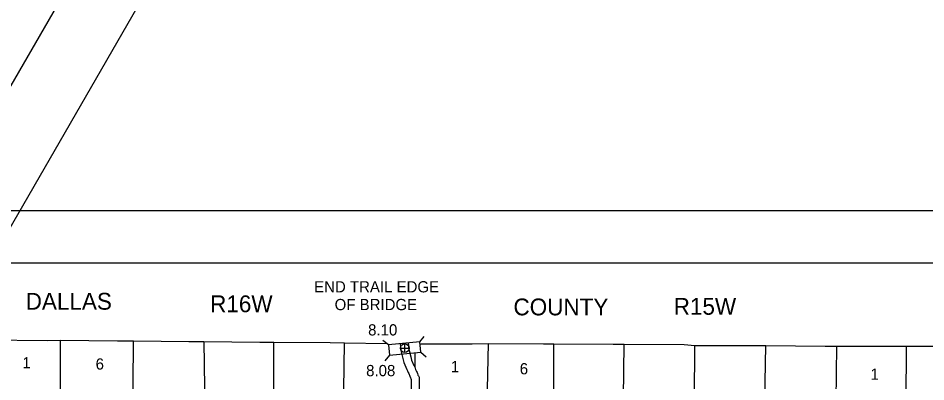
# Model space of a CAD drawing. Extents: x 369523 to 838377, y 495025 to 936819.
# Drawn here: x 667340 to 735755, y 661645 to 689027 of the extents above; entities that cross this region are included whole.
import ezdxf

# ---------------------------------------------------------------- set-up
doc = ezdxf.new("R2010")
doc.units = 0
for name, color, linetype in [('21', 7, 'Continuous'), ('DSN_BRDG_Annotation', 7, 'Continuous'), ('DSN_DRFT_Common-Annotations', 7, 'Continuous'), ('DSN_DRFT_Junk-No-Plot', 7, 'Continuous'), ('Level 1', 7, 'Continuous'), ('Level 15', 7, 'Continuous'), ('Level 21', 7, 'Continuous'), ('Level 22', 7, 'Continuous'), ('Level 6', 7, 'Continuous')]:
    doc.layers.add(name, color=color, linetype=linetype)

msp = doc.modelspace()

# ---------------------------------------------------------------- linework, layer by layer
at = {"layer": '21'}
for p, q in [((715348, 757482), (625588, 602013)), ((623656, 609226), (708796, 756692)), ((542697, 674544), (838377, 674544)), ((833097, 670584), (558537, 670584))]:
    msp.add_line(p, q, dxfattribs=at)
at = {"layer": 'DSN_DRFT_Common-Annotations'}
for p, q in [((696475, 663856), (696475, 664506)), ((696150, 664181), (696800, 664181))]:
    msp.add_line(p, q, dxfattribs=at)
msp.add_circle((696475, 664181), 325, dxfattribs=at)
at = {"layer": 'Level 1'}
for points in [[(696142, 664520), (696193, 663993), (696343, 663400), (696408, 663105), (696627, 662573)], [(696739, 664580), (696786, 664096), (696927, 663538), (696983, 663285), (697153, 662871)], [(696627, 662572), (696695, 662483), (696742, 662350), (696782, 662270), (696820, 662186), (696841, 662136), (696862, 662073), (696905, 661945), (696925, 661905), (696936, 661880), (696958, 661842), (696964, 661829), (696967, 661797), (696965, 661333), (696962, 660427), (696949, 658143), (696942, 656353), (696906, 653832), (696897, 651382), (696888, 648894), (696886, 646041), (696867, 644516)], [(697155, 662870), (697230, 662772), (697296, 662584), (697324, 662528), (697369, 662428), (697404, 662346), (697432, 662261), (697460, 662177), (697468, 662161), (697473, 662150), (697488, 662123), (697503, 662093), (697553, 661993), (697567, 661820), (697565, 661331), (697562, 660424), (697549, 658140), (697542, 656347), (697506, 653827), (697497, 651380), (697488, 648893), (697486, 646037), (697467, 644508)]]:
    msp.add_lwpolyline(points, dxfattribs=at)
at = {"layer": 'Level 15'}
for points in [[(670516, 664770), (670498, 661442), (670513, 656246), (670412, 650747), (670380, 645424)], [(702767, 664536), (702692, 661105), (702706, 660827), (702651, 656443)]]:
    msp.add_lwpolyline(points, dxfattribs=at)
at = {"layer": 'Level 21'}
for p, q in [((697612, 664659), (697948, 665066)), ((695246, 664432), (694839, 664768)), ((695322, 663643), (694986, 663236)), ((697687, 663870), (698095, 663534))]:
    msp.add_line(p, q, dxfattribs=at)
msp.add_lwpolyline([(697612, 664659), (695246, 664432), (695322, 663643), (697687, 663870)], close=True, dxfattribs=at)
at = {"layer": 'Level 22'}
for points in [[(675941, 645438), (675979, 650773), (676016, 656118), (676007, 661399), (676041, 664720)], [(681333, 664675), (681392, 661224), (681360, 656007), (681270, 650692), (681269, 645360)], [(686501, 639908), (686514, 645242), (686453, 650757), (686568, 655875), (686621, 661194), (686617, 664631)], [(691808, 639737), (691846, 645091), (691896, 650512), (691831, 655788), (691896, 661043), (691936, 664586)], [(707670, 653206), (707663, 655441), (707718, 660824), (707725, 664501)], [(712976, 650207), (713007, 655290), (712972, 660442), (713010, 664470)], [(718216, 645104), (718231, 649676), (718250, 655145), (718319, 660327), (718337, 664389)], [(723596, 649646), (723590, 654958), (723631, 660241), (723685, 664373)], [(729009, 664329), (728969, 660219), (728840, 654916), (728886, 649599)], [(697272, 662725), (697276, 663777)]]:
    msp.add_lwpolyline(points, dxfattribs=at)
at = {"layer": 'Level 6'}
for points in [[(660566, 664847), (664267, 664825), (664906, 664815), (669577, 664764), (670516, 664770), (674836, 664730), (676041, 664720), (680216, 664686), (681333, 664675)], [(681333, 664675), (685545, 664638), (686617, 664631), (690852, 664595), (691936, 664586), (695138, 664531)], [(697684, 664513), (701566, 664516), (702767, 664536), (706946, 664500), (707725, 664501), (712191, 664474), (713010, 664470), (717544, 664455), (718337, 664389)], [(718337, 664389), (722832, 664389), (723685, 664373), (728177, 664326), (729009, 664329), (733495, 664331), (734273, 664331), (737253, 664341)], [(734273, 664331), (734245, 660137)]]:
    msp.add_lwpolyline(points, dxfattribs=at)

# ---------------------------------------------------------------- texts
at = {"layer": '21'}
for s, p in [('DALLAS', (667907, 667076)), ('R16W', (681809, 666886)), ('COUNTY', (704673, 666650)), ('R15W', (716750, 666694))]:
    msp.add_text(s, height=1267.2, dxfattribs=at).set_placement(p)
at = {"layer": 'DSN_BRDG_Annotation'}
for s, p in [('END TRAIL EDGE', (689649, 668379)), ('OF BRIDGE', (691195, 667042)), ('8.10', (693718, 665135))]:
    msp.add_text(s, height=844.8, dxfattribs=at).set_placement(p)
at = {"layer": 'DSN_DRFT_Junk-No-Plot'}
msp.add_text('8.08', height=844.8, dxfattribs=at).set_placement((693568, 662070))
at = {"layer": 'Level 22'}
for s, p in [('1', (667660, 662661)), ('6', (673180, 662567)), ('1', (699956, 662372)), ('6', (705147, 662208)), ('1', (731581, 661801))]:
    msp.add_text(s, height=845, dxfattribs=at).set_placement(p)

doc.saveas('drawing.dxf')
